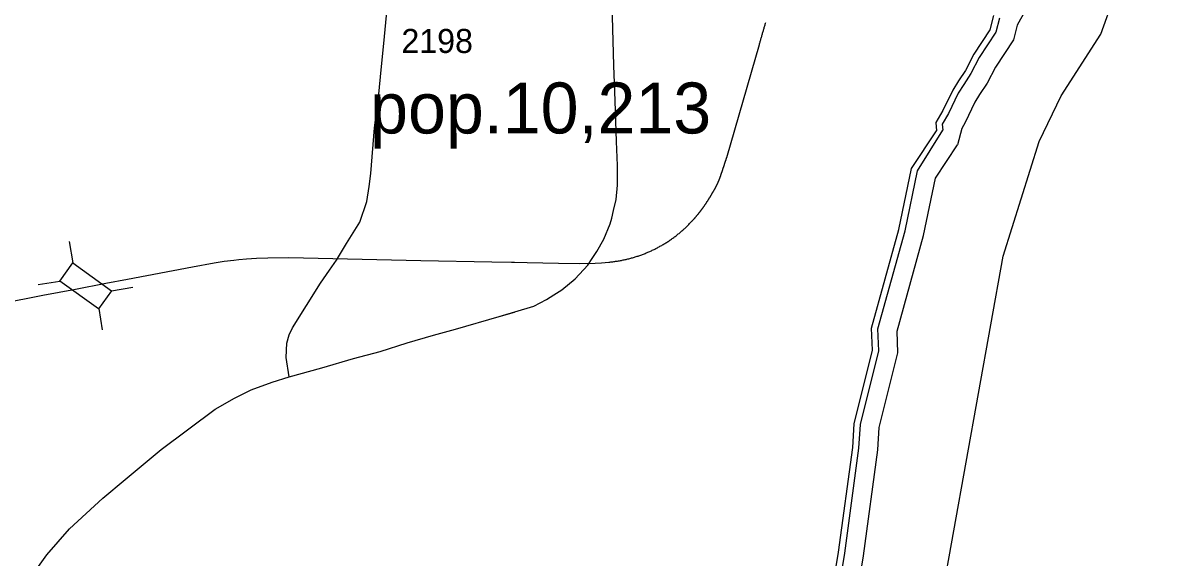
# Model space of a CAD drawing. Extents: x 1364363 to 1407445, y 538563 to 573342.
# Drawn here: x 1396463 to 1402454, y 565438 to 568220 of the extents above; entities that cross this region are included whole.
import ezdxf

# ---------------------------------------------------------------- set-up
doc = ezdxf.new("R2010")
doc.units = 0
for name, color, linetype in [('Default', 7, 'Continuous'), ('Exist Civil Demographics City Label', 7, 'Continuous'), ('Exist Hydrographic Bay Label', 7, 'Continuous'), ('Exist Hydrographic Buffer Line', 7, 'Continuous'), ('Exist Hydrographic Creek Double Shore', 7, 'Continuous'), ('Exist Railroad Mainline', 7, 'Continuous'), ('Exist Road Primary NC Attributed', 7, 'Continuous'), ('Exist Road Secondary Type 51 Attributed', 7, 'Continuous'), ('Exist Road Secondary Type 51 Number Label', 7, 'Continuous')]:
    doc.layers.add(name, color=color, linetype=linetype)

msp = doc.modelspace()

# ---------------------------------------------------------------- linework, layer by layer
at = {"layer": 'Default'}
for p, q in [((1396703.1, 567084.2), (1396721.5, 566972.6)), ((1396703.1, 567084.2), (1396721.5, 566972.6)), ((1396542.4, 566860), (1396654.1, 566878.4)), ((1396542.4, 566860), (1396654.1, 566878.4)), ((1396922.7, 566827.8), (1397034.4, 566846.2)), ((1396922.7, 566827.8), (1397034.4, 566846.2)), ((1396856.8, 566735.8), (1396875.3, 566624.1)), ((1396856.8, 566735.8), (1396875.3, 566624.1))]:
    msp.add_line(p, q, dxfattribs=at)
msp.add_lwpolyline([(1396721.5, 566972.6), (1396923, 566828.2), (1396855.6, 566734.1), (1396654.1, 566878.4)], close=True, dxfattribs=at)
msp.add_lwpolyline([(1396721.5, 566972.6), (1396923, 566828.2), (1396855.6, 566734.1), (1396654.1, 566878.4)], close=True, dxfattribs=at)
at = {"layer": 'Exist Hydrographic Bay Label'}
msp.add_lwpolyline([(1400558.6, 562517.8), (1400738.5, 563154.2), (1400923.6, 563636.3), (1401093.5, 564213.8), (1401239.5, 565221.9), (1401560.4, 567007.6), (1401747.4, 567604.5), (1401861.4, 567841.8), (1402068.4, 568162.6), (1402139.5, 568361.4), (1402251.4, 568575.8), (1402279.4, 569126.7), (1402359.4, 569341.8), (1402893.4, 570164.7), (1402945.4, 570288.4), (1403031.4, 570769.2), (1403098.3, 571627.8), (1403169.3, 571793.8), (1403414.3, 571979.3)], dxfattribs=at)
at = {"layer": 'Exist Hydrographic Buffer Line'}
for points in [[(1401674, 568283.1), (1401632.7, 568209.8), (1401613.3, 568132.4), (1401520.7, 567991.4), (1401476.7, 567907), (1401437.9, 567848.7), (1401413.4, 567808.3), (1401362.6, 567703.1), (1401344.5, 567672.3), (1401323.2, 567586.9)], [(1401540.4, 568246.6), (1401521.9, 568172.5), (1401435.7, 568041.3), (1401391.9, 567957.2), (1401354.8, 567901.5), (1401326.7, 567855.2), (1401275.7, 567749.5), (1401243.8, 567695.2), (1401246.6, 567662.4)], [(1400459.4, 563963.7), (1400623.9, 564773), (1400737.2, 565463.3), (1400810.4, 566009.4), (1400817.6, 566131.8), (1400912.8, 566516.3), (1400909.2, 566629.1), (1401050.3, 567139), (1401115, 567451.7), (1401246.6, 567662.4)], [(1400555.9, 563944.1), (1400720.7, 564755.3), (1400834.5, 565448.8), (1400908.5, 565999.9), (1400915.3, 566116.9), (1401011.6, 566505.8), (1401008.1, 566617.3), (1401146.1, 567115.9), (1401207.5, 567413.1), (1401323.2, 567586.9)]]:
    msp.add_lwpolyline(points, dxfattribs=at)
at = {"layer": 'Exist Hydrographic Creek Double Shore'}
for points in [[(1401509.6, 568258.9), (1401491.4, 568185.8), (1401407.4, 568058), (1401363.6, 567973.9), (1401327.1, 567919.1), (1401297.9, 567870.9), (1401246.8, 567765), (1401210.2, 567702.9), (1401213.9, 567659.6)], [(1400427.3, 563970.2), (1400591.6, 564779), (1400704.7, 565468.2), (1400777.7, 566012.5), (1400785, 566136.7), (1400879.9, 566519.8), (1400876.2, 566633), (1401018.4, 567146.7), (1401084.2, 567464.6), (1401213.9, 567659.6)]]:
    msp.add_lwpolyline(points, dxfattribs=at)
at = {"layer": 'Exist Railroad Mainline'}
msp.add_line((1400122.5, 567520.9), (1400292.4, 568108.1), dxfattribs=at)
for points in [[(1400292.4, 568108.1), (1400293.6, 568112.4), (1400294.7, 568116.7), (1400296, 568121), (1400297.3, 568125.2), (1400298.4, 568129.6), (1400299.7, 568133.8), (1400300.8, 568138.1), (1400302, 568142.4), (1400303.2, 568146.7), (1400304.5, 568150.9), (1400305.6, 568155.2), (1400306.8, 568159.5), (1400308.2, 568163.7), (1400309.4, 568168), (1400310.6, 568172.3), (1400311.9, 568176.6), (1400313.1, 568180.8), (1400314.4, 568185.1), (1400315.6, 568189.3), (1400316.9, 568193.6), (1400318.1, 568197.9), (1400319.3, 568202.1), (1400320.7, 568206.4), (1400322, 568210.6), (1400323.2, 568214.9), (1400324.5, 568219.1), (1400325.9, 568223.4)], [(1400087.1, 567413.9), (1400087.5, 567415), (1400087.8, 567416.1), (1400088.2, 567417.1), (1400088.7, 567418.2), (1400089, 567419.3), (1400089.3, 567420.4), (1400089.6, 567421.5), (1400090, 567422.6), (1400090.4, 567423.6), (1400090.7, 567424.7), (1400091.1, 567425.8), (1400091.5, 567426.9), (1400091.8, 567427.9), (1400092.2, 567429), (1400092.7, 567430.1), (1400093, 567431.2), (1400093.4, 567432.3), (1400093.8, 567433.3), (1400094.1, 567434.4), (1400094.4, 567435.5), (1400094.7, 567436.6), (1400095.1, 567437.6), (1400095.5, 567438.7), (1400095.8, 567439.8), (1400096.2, 567440.9), (1400096.7, 567442), (1400097, 567443), (1400097.4, 567444.1), (1400097.8, 567445.2), (1400098.1, 567446.3), (1400098.4, 567447.3), (1400098.7, 567448.4), (1400099.1, 567449.5), (1400099.5, 567450.6), (1400099.8, 567451.6), (1400100.2, 567452.7), (1400100.6, 567453.8), (1400101, 567454.9), (1400101.4, 567456), (1400101.7, 567457.1), (1400102, 567458.1), (1400102.4, 567459.2), (1400102.7, 567460.3), (1400103.1, 567461.4), (1400103.5, 567462.4), (1400103.8, 567463.5), (1400104.2, 567464.6), (1400104.5, 567465.7), (1400104.9, 567466.8), (1400105.3, 567467.9), (1400105.7, 567468.9), (1400106, 567470), (1400106.4, 567471.1), (1400106.8, 567472.2), (1400107, 567473.2), (1400107.4, 567474.3), (1400107.7, 567475.4), (1400108.1, 567476.5), (1400108.5, 567477.5), (1400108.9, 567478.6), (1400109.3, 567479.7), (1400109.5, 567480.8), (1400109.9, 567481.9), (1400110.3, 567483), (1400110.6, 567484.1), (1400111, 567485.1), (1400111.4, 567486.3), (1400111.6, 567487.3), (1400112, 567488.4), (1400112.3, 567489.4), (1400112.7, 567490.6), (1400113.2, 567491.6), (1400113.5, 567492.7), (1400113.8, 567493.8), (1400114.1, 567494.9), (1400114.5, 567495.9), (1400114.9, 567497.1), (1400115.2, 567498.1), (1400115.5, 567499.2), (1400115.9, 567500.3), (1400116.2, 567501.4), (1400116.6, 567502.5), (1400117, 567503.6), (1400117.4, 567504.6), (1400117.7, 567505.7), (1400118, 567506.8), (1400118.4, 567507.9), (1400118.8, 567508.9), (1400119, 567510), (1400119.4, 567511.1), (1400119.7, 567512.2), (1400120.1, 567513.3), (1400120.5, 567514.4), (1400120.7, 567515.4), (1400121.2, 567516.5), (1400121.5, 567517.6), (1400121.9, 567518.7), (1400122.3, 567519.7), (1400122.5, 567520.9)], [(1400044.4, 567330.2), (1400044.9, 567331), (1400045.4, 567331.8), (1400045.9, 567332.6), (1400046.4, 567333.4), (1400046.9, 567334.2), (1400047.3, 567335), (1400047.8, 567335.8), (1400048.4, 567336.6), (1400048.9, 567337.4), (1400049.4, 567338.3), (1400049.9, 567339.1), (1400050.4, 567339.9), (1400050.9, 567340.7), (1400051.3, 567341.5), (1400051.8, 567342.3), (1400052.4, 567343.1), (1400052.9, 567343.9), (1400053.3, 567344.8), (1400053.8, 567345.5), (1400054.2, 567346.5), (1400054.7, 567347.2), (1400055.2, 567348), (1400055.7, 567348.9), (1400056.3, 567349.7), (1400056.7, 567350.5), (1400057.1, 567351.4), (1400057.6, 567352.2), (1400058.1, 567353), (1400058.5, 567353.8), (1400059, 567354.7), (1400059.5, 567355.5), (1400060, 567356.3), (1400060.4, 567357.1), (1400060.9, 567358), (1400061.4, 567358.8), (1400061.8, 567359.6), (1400062.2, 567360.5), (1400062.6, 567361.3), (1400063.1, 567362.2), (1400063.6, 567363), (1400064, 567363.8), (1400064.5, 567364.7), (1400064.9, 567365.5), (1400065.4, 567366.4), (1400065.8, 567367.2), (1400066.2, 567368), (1400066.6, 567368.9), (1400067.1, 567369.7), (1400067.5, 567370.6), (1400068, 567371.4), (1400068.4, 567372.2), (1400068.9, 567373.1), (1400069.3, 567374), (1400069.8, 567374.8), (1400070.1, 567375.7), (1400070.5, 567376.6), (1400071, 567377.4), (1400071.3, 567378.2), (1400071.7, 567379.1), (1400072.2, 567379.9), (1400072.7, 567380.8), (1400073, 567381.7), (1400073.5, 567382.5), (1400073.9, 567383.4), (1400074.3, 567384.2), (1400074.6, 567385.1), (1400075.1, 567385.9), (1400075.5, 567386.8), (1400075.8, 567387.7), (1400076.2, 567388.5), (1400076.7, 567389.4), (1400077.2, 567390.2), (1400077.5, 567391.1), (1400077.9, 567392), (1400078.3, 567392.9), (1400078.6, 567393.7), (1400079, 567394.6), (1400079.4, 567395.5), (1400079.7, 567396.4), (1400080.1, 567397.3), (1400080.5, 567398.1), (1400081, 567399), (1400081.4, 567399.9), (1400081.8, 567400.7), (1400082, 567401.6), (1400082.4, 567402.5), (1400082.7, 567403.4), (1400083.1, 567404.2), (1400083.5, 567405.1), (1400083.8, 567406), (1400084.2, 567406.9), (1400084.7, 567407.8), (1400085, 567408.6), (1400085.4, 567409.5), (1400085.8, 567410.4), (1400086, 567411.3), (1400086.4, 567412.1), (1400086.7, 567413.1), (1400087.1, 567413.9)], [(1399943.5, 567191.5), (1399944.6, 567192.8), (1399945.8, 567194.1), (1399947, 567195.3), (1399948.1, 567196.6), (1399949.2, 567198), (1399950.6, 567199.2), (1399951.6, 567200.5), (1399952.7, 567201.8), (1399953.8, 567203.1), (1399955, 567204.5), (1399956.1, 567205.7), (1399957.4, 567207.1), (1399958.5, 567208.4), (1399959.7, 567209.7), (1399960.7, 567211), (1399961.8, 567212.3), (1399963, 567213.6), (1399964.1, 567215), (1399965.2, 567216.3), (1399966.2, 567217.6), (1399967.4, 567219), (1399968.5, 567220.3), (1399969.6, 567221.6), (1399970.7, 567223), (1399971.9, 567224.3), (1399972.9, 567225.7), (1399974, 567227.1), (1399975.2, 567228.4), (1399976.1, 567229.7), (1399977.2, 567231.1), (1399978.3, 567232.5), (1399979.4, 567233.8), (1399980.5, 567235.2), (1399981.6, 567236.6), (1399982.6, 567237.9), (1399983.8, 567239.3), (1399984.8, 567240.7), (1399985.9, 567242), (1399986.8, 567243.4), (1399987.9, 567244.8), (1399989, 567246.2), (1399990, 567247.6), (1399991, 567249), (1399992.2, 567250.4), (1399993.1, 567251.7), (1399994.1, 567253.1), (1399995.3, 567254.5), (1399996.3, 567255.9), (1399997.2, 567257.3), (1399998.2, 567258.7), (1399999.3, 567260.1), (1400000.3, 567261.6), (1400001.3, 567263), (1400002.3, 567264.4), (1400003.4, 567265.8), (1400004.4, 567267.2), (1400005.4, 567268.6), (1400006.3, 567270.1), (1400007.2, 567271.5), (1400008.3, 567272.9), (1400009.3, 567274.3), (1400010.2, 567275.8), (1400011.2, 567277.2), (1400012.3, 567278.6), (1400013.3, 567280.1), (1400014.1, 567281.5), (1400015.1, 567282.9), (1400016.2, 567284.4), (1400017, 567285.9), (1400018, 567287.3), (1400019, 567288.7), (1400019.9, 567290.2), (1400020.9, 567291.6), (1400021.7, 567293.1), (1400022.7, 567294.6), (1400023.7, 567296), (1400024.6, 567297.5), (1400025.5, 567298.9), (1400026.5, 567300.4), (1400027.3, 567301.9), (1400028.4, 567303.4), (1400029.3, 567304.8), (1400030.1, 567306.3), (1400031, 567307.8), (1400032, 567309.2), (1400032.9, 567310.7), (1400033.7, 567312.3), (1400034.6, 567313.8), (1400035.6, 567315.2), (1400036.5, 567316.7), (1400037.4, 567318.2), (1400038.2, 567319.7), (1400039.1, 567321.2), (1400040, 567322.7), (1400040.9, 567324.2), (1400041.8, 567325.7), (1400042.6, 567327.2), (1400043.5, 567328.7), (1400044.4, 567330.2)], [(1399510.2, 566977), (1399515.1, 566977.4), (1399520.1, 566978), (1399525.2, 566978.5), (1399530.1, 566979.1), (1399535, 566979.7), (1399540, 566980.4), (1399544.9, 566981.1), (1399549.9, 566981.8), (1399554.8, 566982.6), (1399559.7, 566983.4), (1399564.6, 566984.2), (1399569.7, 566985.1), (1399574.5, 566986.1), (1399579.4, 566987), (1399584.2, 566988), (1399589.1, 566989.1), (1399594, 566990.1), (1399598.9, 566991.2), (1399603.7, 566992.3), (1399608.6, 566993.5), (1399613.5, 566994.7), (1399618.4, 566995.9), (1399623.1, 566997.3), (1399628, 566998.5), (1399632.7, 566999.9), (1399637.6, 567001.3), (1399642.4, 567002.7), (1399647.2, 567004.2), (1399651.9, 567005.7), (1399656.6, 567007.2), (1399661.3, 567008.7), (1399666.1, 567010.4), (1399670.9, 567012), (1399675.6, 567013.7), (1399680.3, 567015.4), (1399685, 567017.1), (1399689.6, 567018.9), (1399694.2, 567020.7), (1399698.8, 567022.6), (1399703.5, 567024.4), (1399708.1, 567026.3), (1399712.8, 567028.3), (1399717.4, 567030.3), (1399721.9, 567032.3), (1399726.5, 567034.3), (1399731, 567036.4), (1399735.5, 567038.6), (1399740, 567040.7), (1399744.5, 567042.9), (1399749, 567045.1), (1399753.5, 567047.3), (1399757.9, 567049.6), (1399762.4, 567052), (1399766.7, 567054.3), (1399771.1, 567056.7), (1399775.5, 567059.1), (1399779.8, 567061.5), (1399784.3, 567064), (1399788.5, 567066.5), (1399792.9, 567069.1), (1399797.2, 567071.6), (1399801.4, 567074.3), (1399805.6, 567076.9), (1399809.9, 567079.6), (1399814, 567082.3), (1399818.3, 567084.9), (1399822.4, 567087.7), (1399826.5, 567090.5), (1399830.6, 567093.3), (1399834.8, 567096.2), (1399838.9, 567099.1), (1399842.9, 567102), (1399846.9, 567105), (1399850.9, 567107.9), (1399854.9, 567111), (1399858.9, 567113.9), (1399862.9, 567117), (1399866.8, 567120.1), (1399870.6, 567123.3), (1399874.5, 567126.4), (1399878.4, 567129.6), (1399882.3, 567132.7), (1399886, 567136), (1399889.8, 567139.3), (1399893.5, 567142.6), (1399897.2, 567145.9), (1399901, 567149.3), (1399904.6, 567152.6), (1399908.4, 567156), (1399912, 567159.5), (1399915.6, 567162.9), (1399919.1, 567166.4), (1399922.8, 567169.9), (1399926.3, 567173.4), (1399929.7, 567177), (1399933.2, 567180.6), (1399936.6, 567184.2), (1399940.1, 567187.8), (1399943.5, 567191.5)], [(1396176.9, 566730.1), (1396478.7, 566787.5), (1396566.8, 566805.2), (1396735.5, 566837.1), (1396894.4, 566867.6), (1397006.2, 566888.4), (1397343.5, 566953.1), (1397456.6, 566973.3), (1397509.7, 566981.3), (1397559.2, 566986.7), (1397584.9, 566991.1), (1397625.3, 566994.1), (1397677.8, 566997.1), (1397735.9, 566999.6), (1397845.3, 567000.2), (1398531.9, 566985), (1398901.5, 566978.2), (1399003.6, 566977), (1399018.9, 566976.7)], [(1396176.9, 566730.1), (1396478.7, 566787.5), (1396566.8, 566805.2), (1396735.5, 566837.1), (1396894.4, 566867.6), (1397006.2, 566888.4), (1397343.5, 566953.1), (1397456.6, 566973.3), (1397509.7, 566981.3), (1397559.2, 566986.7), (1397584.9, 566991.1), (1397625.3, 566994.1), (1397677.8, 566997.1), (1397735.9, 566999.6), (1397845.3, 567000.2), (1398531.9, 566985), (1398901.5, 566978.2), (1399003.6, 566977), (1399247.3, 566972.1), (1399357.3, 566969.6), (1399438.1, 566971.5), (1399470.5, 566973.3), (1399510.2, 566977)]]:
    msp.add_lwpolyline(points, dxfattribs=at)
at = {"layer": 'Exist Road Primary NC Attributed'}
for points in [[(1399423, 566996.4), (1399447.5, 567032.9), (1399482.9, 567095.7), (1399517.1, 567176.4), (1399524.5, 567206), (1399534.2, 567245.1), (1399547.7, 567302), (1399555, 567377.9), (1399553.8, 567479.9), (1399548.9, 567604.3), (1399541.6, 567816.6), (1399535.4, 568000.3), (1399529.3, 568254), (1399519.6, 568433), (1399519.6, 568558.7), (1399518.3, 568661.9), (1399509.1, 568819.9), (1399512.8, 568956.4), (1399531.3, 569101.2)], [(1397846.9, 566380.9), (1398016.7, 566427.1), (1398181.7, 566475.7), (1398320.9, 566512.5), (1398460.2, 566556.3), (1398598.3, 566597.8), (1398711.9, 566628.6), (1398939.2, 566693.8), (1399118.8, 566747.2), (1399186, 566782.8), (1399222.7, 566806.5), (1399264.2, 566832.6), (1399335.1, 566890.6), (1399399.8, 566961.8), (1399423, 566996.4)], [(1397846.9, 566380.9), (1398016.7, 566427.1), (1398181.7, 566475.7), (1398320.9, 566512.5), (1398460.2, 566556.3), (1398598.3, 566597.8), (1398711.9, 566628.6), (1398939.2, 566693.8), (1399018.9, 566717.5)], [(1395403.9, 562729.1), (1395416.1, 562769.4), (1395801, 563717.7), (1395880.9, 563904.2), (1395988.5, 564172.2), (1396132.6, 564532.6), (1396191.3, 564685.5), (1396326.7, 565031.4), (1396389.4, 565164.2), (1396486.5, 565314.3), (1396587.6, 565454.3), (1396704.4, 565589.8), (1396877.8, 565748.4), (1396993.9, 565845.9), (1397182.2, 566001.5), (1397462, 566211.3), (1397563.4, 566269.4), (1397648.9, 566312.1), (1397758.9, 566352.4), (1397846.9, 566380.9)], [(1395403.9, 562729.1), (1395416.1, 562769.4), (1395801, 563717.7), (1395880.9, 563904.2), (1395988.5, 564172.2), (1396132.6, 564532.6), (1396191.3, 564685.5), (1396326.7, 565031.4), (1396389.4, 565164.2), (1396486.5, 565314.3), (1396587.6, 565454.3), (1396704.4, 565589.8), (1396877.8, 565748.4), (1396993.9, 565845.9), (1397182.2, 566001.5), (1397462, 566211.3), (1397563.4, 566269.4), (1397648.9, 566312.1), (1397758.9, 566352.4), (1397846.9, 566380.9)]]:
    msp.add_lwpolyline(points, dxfattribs=at)
at = {"layer": 'Exist Road Secondary Type 51 Attributed'}
for points in [[(1398093.9, 566987.3), (1398145.3, 567073.1), (1398214.8, 567185), (1398251.4, 567292.9), (1398263.6, 567371.1), (1398272.2, 567438.7), (1398290.5, 567674.6), (1398313.7, 567850.1), (1398326.1, 567976.4), (1398339.8, 568114.6), (1398365.1, 568387.9), (1398394.2, 568643)], [(1398093.9, 566987.3), (1398145.3, 567073.1), (1398214.8, 567185), (1398251.4, 567292.9), (1398263.6, 567371.1), (1398272.2, 567438.7), (1398290.5, 567674.6), (1398313.7, 567850.1), (1398326.1, 567976.4), (1398339.8, 568114.6), (1398365.1, 568387.9), (1398394.2, 568643)], [(1397846.9, 566380.9), (1397832.1, 566480.8), (1397835.3, 566555.6), (1397847.7, 566599.2), (1397864.9, 566635.1), (1398009.8, 566867.3), (1398056.5, 566935.9), (1398093.9, 566987.3)], [(1397846.9, 566380.9), (1397832.1, 566480.8), (1397835.3, 566555.6), (1397847.7, 566599.2), (1397864.9, 566635.1), (1398009.8, 566867.3), (1398056.5, 566935.9), (1398093.9, 566987.3)]]:
    msp.add_lwpolyline(points, dxfattribs=at)

# ---------------------------------------------------------------- texts
at = {"layer": 'Exist Civil Demographics City Label'}
msp.add_text('pop.10,213', height=265, dxfattribs=at).set_placement((1398268.1, 567646.1))
msp.add_text('pop.10,213', height=265, dxfattribs=at).set_placement((1398268.1, 567646.1))
at = {"layer": 'Exist Road Secondary Type 51 Number Label'}
msp.add_text('2198', height=125, dxfattribs=at).set_placement((1398430.9, 568064.7))
msp.add_text('2198', height=125, dxfattribs=at).set_placement((1398430.9, 568064.7))

doc.saveas('drawing.dxf')
